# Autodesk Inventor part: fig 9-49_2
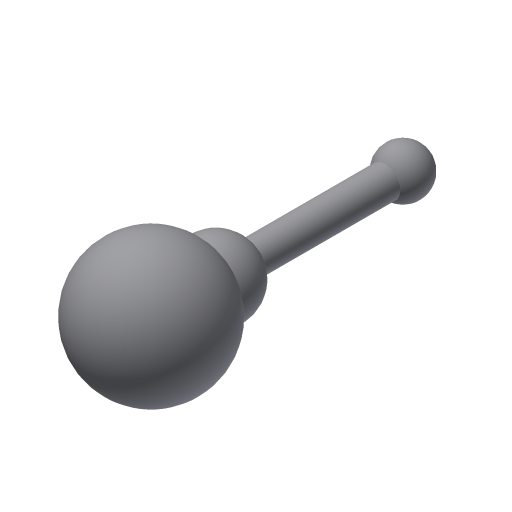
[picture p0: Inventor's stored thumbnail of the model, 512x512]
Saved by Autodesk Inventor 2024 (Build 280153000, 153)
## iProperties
Created: 2013-03
Part Number: fig 9-49_2
Material: Generic
Document SubType Name: Modeling
Designer: CADCIM
Density: 1 g/cm^3
Appearance: Default
Author: CADCIM
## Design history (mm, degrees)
sketch "Sketch1"
  geometry: L1 (0, 5)-(0, -5); A1 r 5 centre (0, 0) between (0, -5) and (0, 5); 1 further point
  constraints: 2 end point, 2 point on circle, 1 centre point, 1 coincident, 1 vertical
  dimensions: "d0" = 10 diameter of A1
revolve "Revolution1" sketch "Sketch1" stored, may be unused: angle "d2" = 90 deg
sketch "Sketch2"
  geometry: L1 (0, 20.921)-(0, 2.139); L2 (1.175, 7.426)-(1.175, 17.742); A1 r 1.807 centre (0, 19.115) between (1.175, 17.742) and (0, 20.921); A2 r 2.774 centre (0, 4.913) between (0, 2.139) and (1.175, 7.426); 1 further point
  constraints: 4 end point, 4 point on circle, 2 centre point, 1 parallel, 1 vertical
revolve "Revolution2" sketch "Sketch2" stored, may be unused: angle "d3" = 90 deg
body "Solid1"
